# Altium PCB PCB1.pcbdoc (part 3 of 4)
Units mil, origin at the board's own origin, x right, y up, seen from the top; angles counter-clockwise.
Board outline 2559.1 x 3937 mil, 4 copper layers (Top Layer, Inner1, Inner2, Bottom Layer), stack 102.8 mil thick; 377 components, 358 nets, 1639 pads, 361 vias.
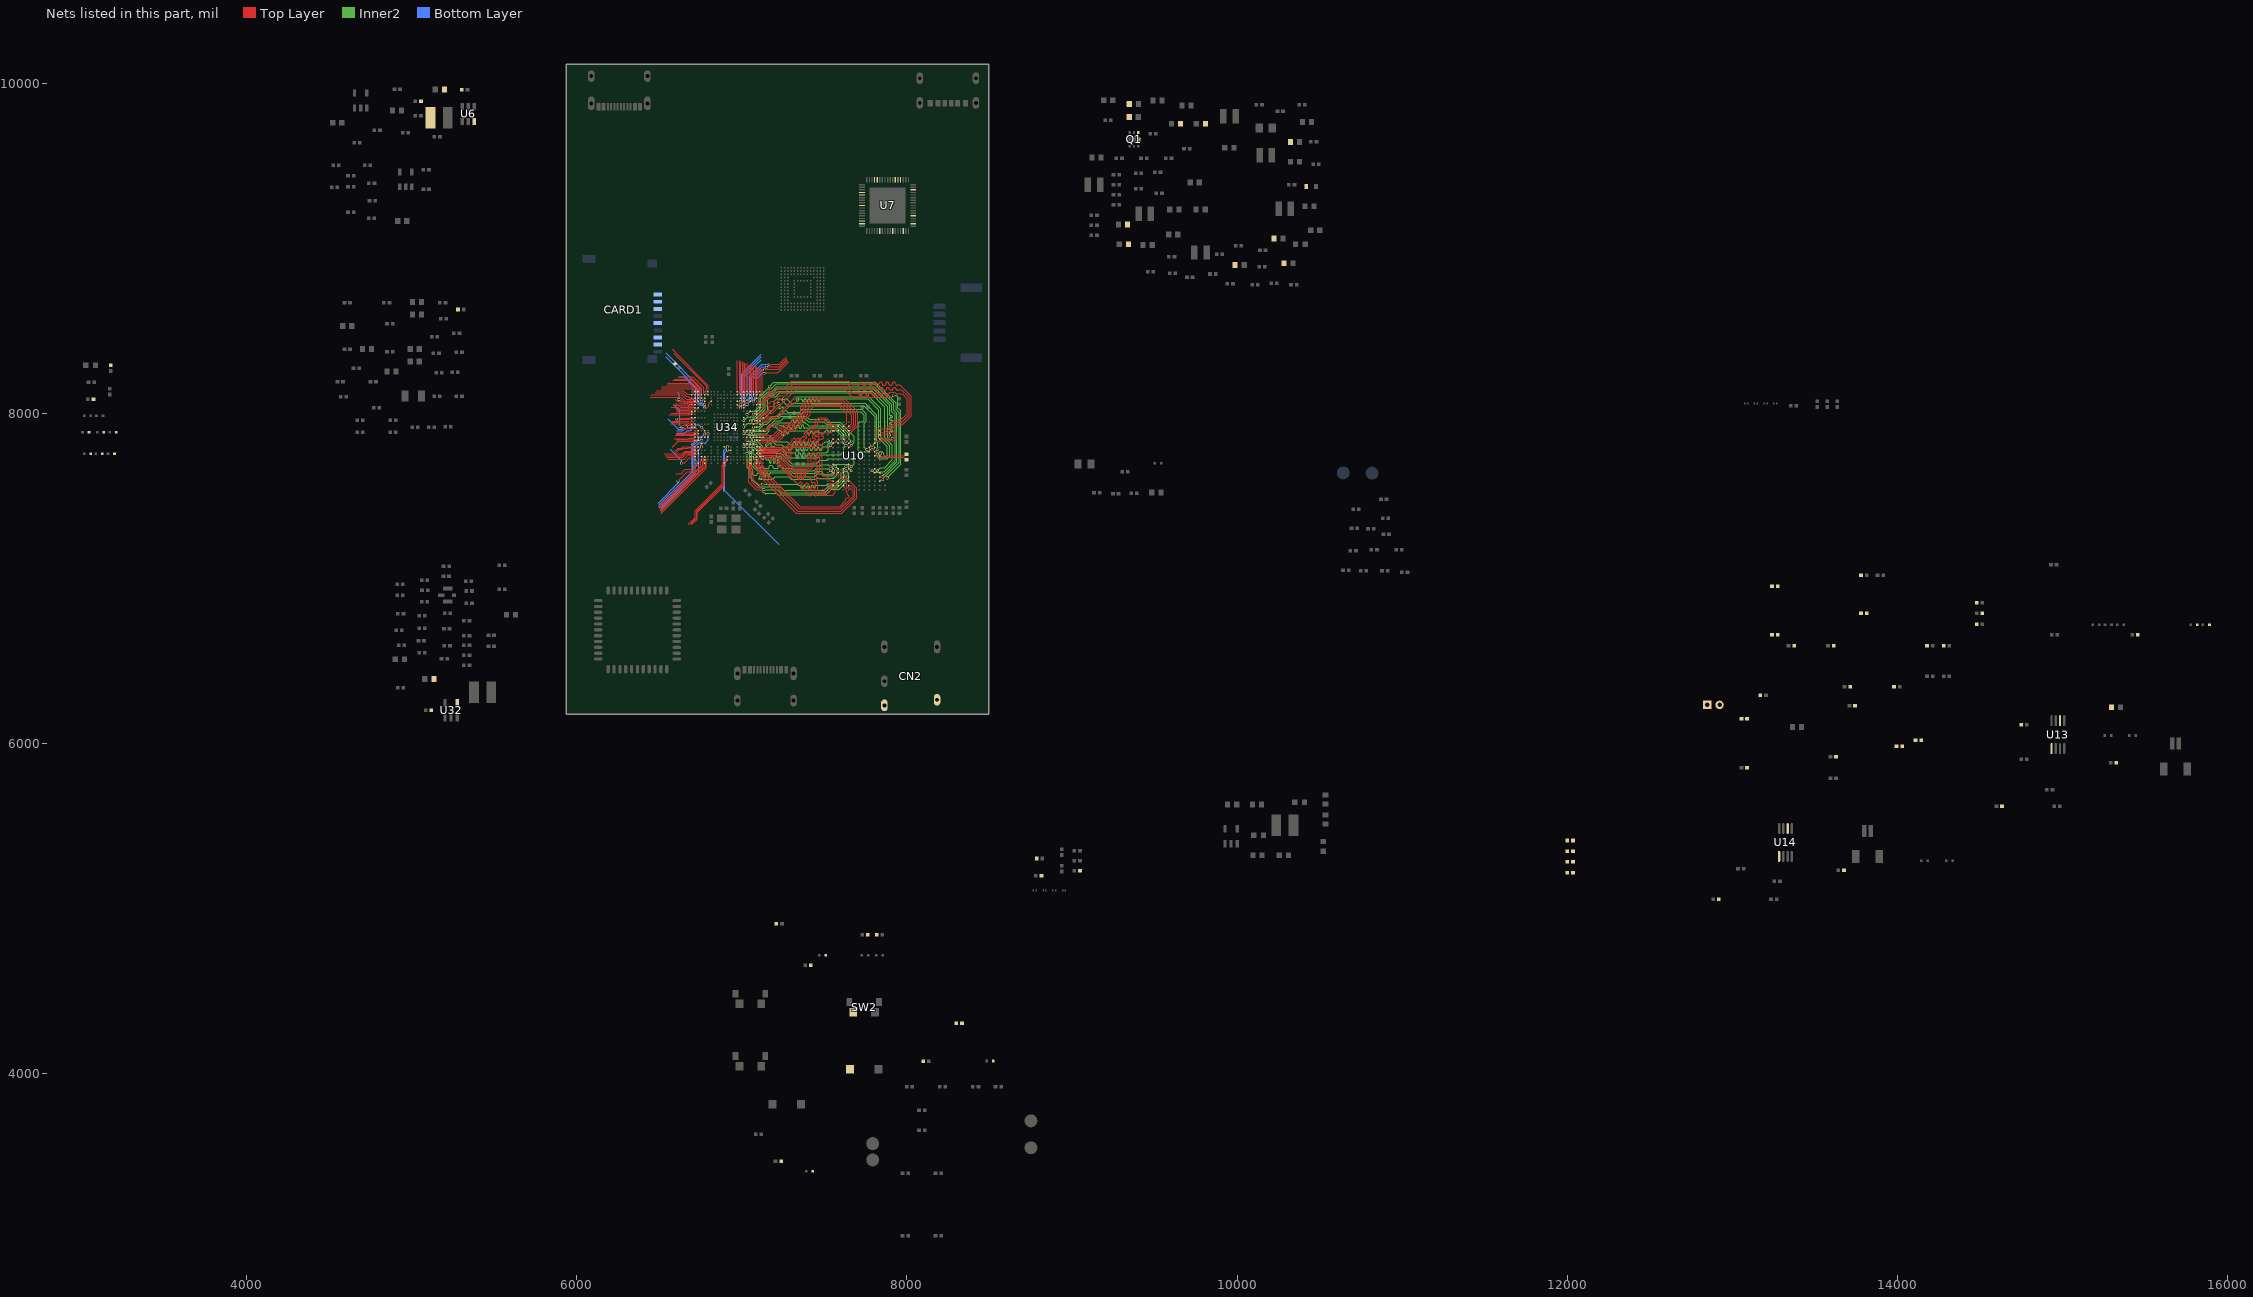
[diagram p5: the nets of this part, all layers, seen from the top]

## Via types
v1: diameter 16, hole 11.8, Top Layer to Bottom Layer, 361 vias

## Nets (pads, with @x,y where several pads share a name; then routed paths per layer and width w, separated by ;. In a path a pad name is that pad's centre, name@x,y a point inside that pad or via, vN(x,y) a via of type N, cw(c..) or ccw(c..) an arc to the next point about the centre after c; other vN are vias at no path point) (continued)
HP-DET: R116.2 U34.C11 | length 272.9
  Top Layer w3.5: v1(6624,7918.6) 6639.2,7903.4 6671.6,7903.4 6673,7904.8 6727.1,7904.8 U34.C11@6736.9,7895
  Bottom Layer w4: 6587.2,8052.4 6624,8015.6 v1(6624,7918.6)
HPOUTFB: C169.1 C170.2 C172.1 R111.1 R112.1 R119.2 U34.B17 | length 149.9
  Top Layer w3.5: 6663.1,7996.4 6678.1,7996.4 6684.9,8003.2 6707.3,8003.2 U34.B17@6717.2,8013.1
  Top Layer w4: 6574.2,7996.4 6663.1,7996.4
HPOUTFB-1: CN2.2 D26.2 R110.2 R111.2
HPOUTL: C157.2 C175.1 R115.1 U34.A17 | length 97.5
  Top Layer w3.5: 6662.5,8005.1 6676.8,8005.1 6684.8,8013.1 U34.A17@6697.5,8013.1
  Top Layer w4: 6603.3,8005.1 6662.5,8005.1
HPOUTR: C152.2 C174.1 R117.1 U34.A16 | length 137.8
  Top Layer w3.5: 6663.8,7988.6 6680.7,7988.6 6685.5,7993.4 U34.A16@6697.5,7993.4
  Top Layer w4: 6561.7,7988.6 6663.8,7988.6
HS-MIC: C168.1 C171.2 C172.2 R109.1 R110.1 R113.1 U34.A15 | length 94.4
  Top Layer w3.5: 6681.2,7969.6 6684.4,7969.6 6688.5,7973.7 U34.A15@6697.5,7973.7
  Top Layer w4: v1(6606.9,7964.5) 6619.8,7964.5 6624.8,7969.6 6681.2,7969.6
HS-MIC-1: CN2.1 D25.2 R109.2 R112.2
I2S0-BCLK: U34.D2 | length 396.5
  Top Layer w3.5: 6748.3,7677.3 6753.1,7682.1 6753.1,7709.4 6756.6,7712.9 U34.D2@6756.6,7717.8
  Top Layer w4: 6497.8,7430.9 6690.8,7623.8 6694.8,7623.8 6748.3,7677.3
I2S0-DIN: U34.E1 | length 405.1
  Top Layer w3.5: 6768.2,7662.4 6768.5,7662.4 6776.3,7670.1 U34.E1@6776.3,7698.1
  Top Layer w4: 6509.5,7403.7 6768.2,7662.4
I2S0-DOUT: R123.1 U13.1 U14.1 U34.E2 | length 417.9
  Top Layer w3.5: 6760.3,7665.6 6767.1,7672.4 6767.1,7703.6 6773.4,7710 6773.4,7715.4 U34.E2@6776.1,7718
  Top Layer w4: 6506.5,7411.8 6760.3,7665.6
I2S0-LRCK: U34.E3 | length 460.1
  Top Layer w3.5: 6775.5,7657.6 6785.5,7667.6 6785.5,7714.2 6786.1,7714.8 6786.1,7727.7 U34.E3@6776.3,7737.5
  Top Layer w4: 6512.6,7394.8 6775.5,7657.6
I2S0-MCLK: U34.D3 | length 430.3
  Top Layer w3.5: 6756.1,7674.5 6760.1,7678.5 6760.1,7706.5 6766.4,7712.9 6766.4,7727.6 U34.D3@6756.6,7737.5
  Top Layer w4: 6502.2,7420.6 6756.1,7674.5
KD-EINT: R99.2 R100.1 R101.2 U34.B3 | length 210.2
  Top Layer w3.5: v1(6634.9,7698.3) 6650.8,7698.3 6680.5,7728 6702.2,7728 6710,7735.8 U34.B3@6716.3,7735.8
  Bottom Layer w4: 6566.2,7783.1 6634.9,7714.4 v1(6634.9,7698.3)
LCD-CLK: U34.W21 | length 387.5
  Top Layer w4: U34.W21@7051.8,8091.8 v1(7071.5,8091.8) ; v1(7137,8262.4) 7221.6,8262.4 7276.9,8317.7
  Bottom Layer w4: v1(7071.5,8091.8) 7071.5,8209.4 7124.6,8262.4 v1(7137,8262.4)
LCD-D2: U34.V22 | length 187.7
  Top Layer w3.5: U34.V22@7032.2,8111.5 7042,8121.4 7042,8154.3
  Top Layer w4: 7042,8154.3 7042,8295.2
LCD-D3: U34.V23 | length 168.2
  Top Layer w4: U34.V23@7032.2,8131.2 7032.2,8299.4
LCD-D4: U34.W22 | length 182.1
  Top Layer w3.5: U34.W22@7051.8,8111.5 7061.7,8121.4 7061.7,8150.4
  Top Layer w4: 7061.7,8150.4 7061.7,8289.5
LCD-D5: U34.W23 | length 161.2
  Top Layer w4: U34.W23@7051.8,8131.2 7051.8,8292.4
LCD-D6: U34.AA22 | length 168.1
  Top Layer w3.5: U34.AA22@7091.2,8111.5 7101,8121.4 7101,8146.6
  Top Layer w4: 7101,8146.6 7101,8275.6
LCD-D7: U34.AA23 | length 147.4
  Top Layer w4: U34.AA23@7091.2,8131.2 7091.2,8278.6
LCD-D10: U34.Y22 | length 174.5
  Top Layer w3.5: U34.Y22@7071.5,8111.5 7081.4,8121.4 7081.4,8152.5
  Top Layer w4: 7081.4,8152.5 7081.4,8281.9
LCD-D11: U34.Y23 | length 154.6
  Top Layer w4: U34.Y23@7071.5,8131.2 7071.5,8285.8
LCD-D12: U34.AB22 | length 159.9
  Top Layer w3.5: U34.AB22@7110.9,8111.5 7120.7,8121.3 7120.7,8152.4
  Top Layer w4: 7120.7,8152.4 7120.7,8267.3
LCD-D13: U34.AB23 | length 140.8
  Top Layer w4: U34.AB23@7110.9,8131.2 7110.9,8272
LCD-D14: U34.R22 | length 210.3
  Top Layer w4: U34.R22@6973.1,8111.5 6984,8122.5 6984,8317.3
LCD-D15: U34.R23 | length 187.5
  Top Layer w4: U34.R23@6973.1,8131.2 6973.1,8318.7
LCD-D18: U34.T21 | length 222.7
  Top Layer w3.5: U34.T21@6992.8,8091.8 7002.6,8101.7 7002.6,8154.6
  Top Layer w4: 7002.6,8154.6 7002.6,8310.5
LCD-D19: U34.T22 | length 201.7
  Top Layer w4: U34.T22@6992.8,8111.5 6992.8,8313.2
LCD-D20: U34.U22 | length 195.9
  Top Layer w3.5: U34.U22@7012.5,8111.5 7022.3,8121.4 7022.3,8152.2
  Top Layer w4: 7022.3,8152.2 7022.3,8303.4
LCD-D21: U34.U23 | length 176.1
  Top Layer w4: U34.U23@7012.5,8131.2 7012.5,8307.3
LCD-D22: U34.U21 | length 152.2
  Top Layer w4: U34.U21@7012.5,8091.8 v1(7032.2,8091.8)
  Bottom Layer w4: v1(7032.2,8091.8) 7032.2,8224.3
LCD-D23: U34.U20 | length 365.8
  Top Layer w4: v1@6992.8,8052.5 U34.U20@7012.5,8072.2
  Bottom Layer w4: v1@6992.8,8052.5 7006.6,8066.3 7006.6,8229.2 7116.6,8339.2
  other v1: 6992.5,8052.5
LCD-DE: U34.W20 | length 397.1
  Top Layer w4: U34.W20@7051.8,8072.2 v1(7071.5,8072.2) ; v1(7136.3,8242) 7215.9,8242 7283.3,8309.4
  Bottom Layer w4: v1(7071.5,8072.2) 7086.7,8087.4 7086.7,8202.3 7126.1,8241.7 7136,8241.7 v1(7136.3,8242)
LCD-HSYNC: U34.U19 | length 451.6
  Top Layer w4: U34.U19@7012.5,8052.5 v1(7032.2,8072.2) ; v1(7167.6,8294.2) 7225.9,8294.2 7267.3,8335.6
  Bottom Layer w4: v1@7032.2,8072.3 7045.7,8085.8 7045.7,8221.7 7118.2,8294.2 v1(7167.6,8294.2)
LCD-PWM: U34.R19 | length 371.5
  Top Layer w4: U34.R19@6973.1,8052.5 v1(6992.8,8032.8)
  Bottom Layer w4: v1(6992.8,8032.8) 7017.7,8057.7 7017.7,8225 7117.5,8324.8
LCD-RST: U34.R20 | length 353.2
  Top Layer w4: U34.R20@6973.1,8072.2 v1(6992.8,8072.2)
  Bottom Layer w4: v1(6992.8,8072.2) 6996.8,8076.2 6996.8,8235.4 7116.1,8354.6
LCD-VSYNC: U34.U18 | length 462.3
  Top Layer w4: U34.U18@7012.5,8032.8 v1(7032.2,8052.5) ; v1(7150.7,8278.2) 7224.1,8278.2 7272.8,8326.9
  Bottom Layer w4: v1(7032.2,8052.5) 7057.3,8077.6 7057.3,8214.4 7121.1,8278.2 v1(7150.7,8278.2)
LRADC: C158.2 D38.2 R131.1 R134.2 R135.1 U34.E11 | length 204.5
  Top Layer w4: v1(6756.6,7914.7) U34.E11@6776.3,7895
  Bottom Layer w4: 6606.6,7878.4 6653.5,7878.4 6669.2,7894.1 6686.8,7894.1 6721.4,7928.7 6742,7928.7 6756,7914.7 v1(6756.6,7914.7)
MBIAS: C180.1 R122.2 U34.B15 | length 146.2
  Top Layer w3.5: 6680.7,7959.2 6685.6,7959.2 6690.3,7963.9 6707.3,7963.9 U34.B15@6717.2,7973.7
  Top Layer w4: 6580.9,7949.8 6621.1,7949.8 6630.5,7959.2 6680.7,7959.2
MCSI-MCLK: R29.1
MCSI-RST-F: U34.E22 | length 223.6
  Top Layer w3.5: 6765.8,8152.4 6765.8,8121.9 U34.E22@6776.3,8111.5
  Top Layer w4: 6618.1,8219.8 6703,8219.8 6765.8,8157 6765.8,8152.4
MCSI-RST-R: U34.E21 | length 413.8
  Top Layer w4: v1(6756.8,8071.5) 6756.8,8072.4 U34.E21@6776.3,8091.8
  Bottom Layer w4: 6538.8,8366.6 6746.6,8158.8 6746.6,8081.7 v1(6756.8,8071.5)
MCSI-SCK: U34.E20 | length 415.2
  Top Layer w4: v1(6776.3,8052.5) U34.E20@6776.3,8072.2
  Bottom Layer w4: 6543.1,8338.3 6631.4,8250 6632.8,8250 6640.7,8242 6640.7,8240.7 6735.1,8146.3 6735.1,8072.6 6750,8057.6 6771.1,8057.6 v1(6776.3,8052.5)
MCSI-SDA: U34.G20 | length 344.5
  Top Layer w4: v1(6776.3,8032.8) 6776.8,8032.2 6789.6,8032.2 6797.7,8040.3 6797.7,8054.4 6815.4,8072.2 U34.G20@6815.6,8072.2
  Bottom Layer w4: 6618.9,8219.4 6650.7,8219.4 6722.3,8147.7 6722.3,8070.2 6745,8047.6 6761.5,8047.6 v1(6776.3,8032.8)
MCSI-STBY-F: U34.F22 | length 336.9
  Top Layer w3.5: 6786.1,8148.1 6786.1,8121.3 U34.F22@6795.9,8111.5
  Top Layer w4: 6589.1,8362.7 6786.1,8165.7 6786.1,8148.1
MCSI-STBY-R: U34.F23 | length 344.6
  Top Layer w4: 6579.4,8386.1 6795.9,8169.6 U34.F23@6795.9,8131.2
MCSIA-CKN: U34.A22 | length 224.5
  Top Layer w4: 6482.2,8132.6 6650.6,8132.6 6672.3,8110.9 6696.9,8110.9 U34.A22@6697.5,8111.5
MCSIA-CKP: U34.A21 | length 232.5
  Top Layer w4: 6476.6,8119.7 6645.9,8119.7 6666.7,8098.9 6677.1,8098.9 6684.2,8091.8 U34.A21@6697.5,8091.8
MCSIA-D0N: U34.D21 | length 245
  Top Layer w3.5: 6746.7,8143.4 6746.8,8101.6 U34.D21@6756.6,8091.8
  Top Layer w4: 6581.8,8195.3 6699.8,8195.3 6746.7,8148.4 6746.7,8143.4
MCSIA-D0P: U34.D22 | length 228.9
  Top Layer w4: 6590.4,8206.3 6701.8,8206.3 6756.6,8151.5 U34.D22@6756.6,8111.5
MCSIA-D1N: U34.C22 | length 227.3
  Top Layer w3.5: 6727,8139.7 6727,8121.4 U34.C22@6736.9,8111.5
  Top Layer w4: 6545.5,8169.7 6698.9,8169.7 6727,8141.5 6727,8139.7
MCSIA-D1P: U34.C23 | length 215.2
  Top Layer w4: 6551,8182.3 6699.6,8182.3 6736.9,8145 U34.C23@6736.9,8131.2
MCSIA-D2N: U34.B21 | length 282
  Top Layer w3.5: 6663.2,8086.2 6666.8,8082.7 6703.1,8082.7 6712.2,8091.8 U34.B21@6717.2,8091.8
  Top Layer w4: 6449.4,8108 6641.4,8108 6663.2,8086.2
MCSIA-D2P: U34.C21 | length 309.8
  Top Layer w3.5: 6662,8073.1 6672.1,8073.1 6674.6,8075.7 6705.9,8075.7 6712.3,8082 6727.1,8082 U34.C21@6736.9,8091.8
  Top Layer w4: 6444.8,8097.1 6632.4,8097.1 6656.4,8073.1 6662,8073.1
MCSIA-D3N: U34.B22 | length 227.1
  Top Layer w3.5: 6670.8,8144.9 6699,8144.9 6707.3,8136.5 6707.3,8121.4 U34.B22@6717.2,8111.5
  Top Layer w4: 6512.8,8144.9 6670.8,8144.9
MCSIA-D3P: U34.B23 | length 215.6
  Top Layer w4: 6516.9,8157.7 6698.1,8157.7 6717.2,8138.7 U34.B23@6717.2,8131.2
MCSIB-CKN: U34.A19 | length 108.1
  Top Layer w3.5: 6674.9,8045.9 6675.3,8045.9 6681.9,8052.5 U34.A19@6697.5,8052.5
  Top Layer w4: 6596.9,8057.5 6624.5,8057.5 6636.1,8045.9 6674.9,8045.9
MCSIB-CKP: U34.B19 | length 143.4
  Top Layer w3.5: 6675.7,8036.2 6682.4,8042.9 6707.6,8042.9 U34.B19@6717.2,8052.5
  Top Layer w4: 6585,8047 6619.9,8047 6630.7,8036.2 6675.7,8036.2
MCSIB-D0N: U34.B20 | length 160
  Top Layer w3.5: 6667.7,8064 6673.1,8064 6677.8,8068.7 6709.1,8068.7 6712.6,8072.2 U34.B20@6717.2,8072.2
  Top Layer w4: v1(6619.3,8082.9) 6619.6,8083.1 6631.5,8083.1 6650.7,8064 6667.7,8064
  Bottom Layer w4: 6608.5,8129.2 6619.3,8118.3 v1(6619.3,8082.9)
MCSIB-D0P: U34.C20 | length 157.6
  Top Layer w3.5: 6672.3,8055 6674.5,8055 6681.1,8061.7 6712,8061.7 6712,8062.3 6727,8062.3 U34.C20@6736.9,8072.2
  Top Layer w4: 6598.2,8082.5 6612,8068.7 6629.8,8068.7 6643.5,8055 6672.3,8055
MCSIB-D1N: U34.B18 | length 151.4
  Top Layer w3.5: 6677.7,8026.4 6684.1,8032.8 U34.B18@6717.2,8032.8
  Top Layer w4: 6572.7,8036.7 6612.9,8036.7 6623.3,8026.4 6677.7,8026.4
MCSIB-D1P: U34.C18 | length 148.4
  Top Layer w3.5: 6676.9,8015.5 6682.1,8020.7 6685.7,8020.7 6689.2,8024.2 6707.2,8024.2 6708.5,8022.9 6727,8022.9 U34.C18@6736.9,8032.8
  Top Layer w4: 6601.4,8026.9 6612.9,8015.5 6676.9,8015.5
MIC1N-MIC: C153.2 C154.2 C177.1 MIC1.2 R127.2
MIC1P-MIC: C177.2 C178.1 C179.2 MIC1.1 R124.2
MICIN1N: C153.1 U34.A13 | length 134.6
  Top Layer w4: 6569,7932.1 6631.9,7932.1 6640.5,7940.7 6675,7940.7 6681.4,7934.4 U34.A13@6697.5,7934.4
MICIN1P: C179.1 U34.B13 | length 151.4
  Top Layer w3.5: 6680,7949.2 6685,7944.2 6707.4,7944.2 U34.B13@6717.2,7934.4
  Top Layer w4: 6575.3,7941 6628.6,7941 6636.8,7949.2 6680,7949.2
MICIN2N: C169.2 U34.A12 | length 103
  Top Layer w4: v1(6663.7,7918) 6667.1,7914.7 U34.A12@6697.5,7914.7
  Bottom Layer w4: 6607.6,7894.4 6643.5,7894.4 6663.7,7914.6 v1(6663.7,7918)
MICIN2P: C168.2 U34.B12 | length 219.8
  Top Layer w3.5: 6669.1,7932.4 6677,7924.5 6707.3,7924.5 U34.B12@6717.2,7914.7
  Top Layer w4: v1(6644,7919) 6657.5,7932.4 6669.1,7932.4
  Bottom Layer w4: 6550.9,7967.5 6616.2,7902.2 6638.5,7902.2 6644,7907.7 v1(6644,7919)
MOTOR-DRV: U34.C1 | length 361.4
  Top Layer w4: v1(6614.1,7588.5) 6614.1,7588.6 6668.8,7643.3 6689.9,7643.3 6736.9,7690.3 U34.C1@6736.9,7698.1
  Bottom Layer w4: 6490.5,7451.1 6614.1,7574.7 v1(6614.1,7588.5)
MPU6050-INT: U34.M2 | length 480.5
  Top Layer w3.5: 6887,7556.1 6894.8,7563.9 6894.8,7674.5 6903.7,7683.4 6903.7,7702.7 6914,7713 U34.M2@6914,7717.8
  Top Layer w4: 6698.8,7326.4 6731.8,7359.4 6731.8,7400.9 6887,7556.1
PA-VDD: C151.2 C156.2 L10.1 U13.6 U14.6
PH2: U34.B6 | length 132.5
  Top Layer w4: 6596.1,7769 6615.9,7788.8 6634.9,7788.8 6642.7,7796.6 U34.B6@6717.2,7796.6
PH3: U34.B5 | length 196.3
  Top Layer w3.5: 6638.1,7750.5 6655.3,7767.7 6702.2,7767.7 6711.3,7776.9 U34.B5@6717.5,7776.9
  Top Layer w4: 6532.2,7750.5 6638.1,7750.5
PH4: U34.C6 | length 151.9
  Top Layer w3.5: 6672.1,7786.7 6727,7786.7 U34.C6@6736.9,7796.6
  Top Layer w4: 6600.3,7759.7 6621.3,7780.7 6638.6,7780.7 6644.6,7786.7 6672.1,7786.7
PH5: U34.C5 | length 213
  Top Layer w3.5: 6639.9,7741.3 6659.3,7760.7 6705.1,7760.7 6711.4,7767 6727,7767 U34.C5@6736.9,7776.9
  Top Layer w4: 6538.6,7741.3 6639.9,7741.3
PH6: U34.F9 | length 612.4
  Top Layer w4: U34.F9@6795.9,7855.6 v1(6795.9,7875.3)
  Bottom Layer w4: 6508.9,7425.8 6716.5,7633.4 6716.5,7798.1 6736.8,7818.4 6778.4,7818.4 6795.9,7835.9 v1(6795.9,7875.3)
PH7: U34.C4 | length 202.2
  Top Layer w3.5: 6667.8,7738.2 6676.3,7746.7 6710.9,7746.7 6710.9,7747.3 6728.7,7747.3 U34.C4@6738.5,7757.1
  Top Layer w4: 6551,7722.4 6652,7722.4 6667.8,7738.2
PH8: U34.E9 | length 578.3
  Top Layer w4: U34.E9@6776.3,7855.6 v1(6776.3,7875.3)
  Bottom Layer w4: 6495.5,7439.5 6699.1,7643.1 6699.1,7809.2 6745.8,7856 6756.3,7856 6775.6,7875.3 v1(6776.3,7875.3)
PH9: U34.D9 | length 540.9
  Top Layer w4: v1(6756.6,7835.9) U34.D9@6756.6,7855.6
  Bottom Layer w4: 6500.8,7431 6707.8,7637.9 6707.8,7804.7 6739,7835.9 v1(6756.6,7835.9)
PH10: U34.B4 | length 181.8
  Top Layer w3.5: 6643.4,7732.5 6664.5,7753.7 6708,7753.7 6710.6,7756.3 6716.3,7756.3 U34.B4@6717.2,7757.2
  Top Layer w4: 6545.7,7732.5 6643.4,7732.5
PH11: U34.D7 | length 506.7
  Top Layer w4: v1(6756.6,7796.6) U34.D7@6756.6,7816.3
  Bottom Layer w4: 6509.2,7412.1 6739.3,7642.3 6739.3,7779.4 v1(6756.6,7796.6)
PH13: U34.B2 | length 179.7
  Top Layer w3.5: 6717.3,7683.4 6727,7693.1 6727,7709.9 U34.B2@6719.4,7717.5
  Top Layer w4: 6599.2,7634.4 6632.9,7634.4 6656,7657.5 6691.4,7657.5 6717.3,7683.4
PMU-SCK: U7.47 U34.N5 | length 737
  Top Layer w4: v1@6914,7776.9 U34.N5@6933.7,7776.9
  Bottom Layer w4: v1(6914.1,7776.9) 6898.2,7761 6898.2,7530.9 7226.8,7202.3
PMU-SDA: U7.48 U34.L6 | length 301.8
  Top Layer w4: U34.L6@6894.4,7796.6 v1@6914.2,7796.6
  Bottom Layer w4: 6890.7,7524.4 6890.7,7773 v1(6914.3,7796.6)
PS: C59.2 C60.1 C67.2 C68.2 C71.1 C72.1 C80.1 C85.2 C87.2 C94.1 C95.1 C101.1 C164.2 L3.2 LED1.2 Q1.4 Q1.8 R33.2 R169.2 U6.3 U7.6 U7.11 U7.15 U7.19 U7.22 U7.32 U7.38 U7.39 U7.40 U7.55 U7.56 U7.66 U7.67 U32.4
PWRON: C182.1 R141.1 U7.60
PWRON-KEY: D37.2 R141.2 SW2.3
RESET-KEY: D36.2 R140.2 SW4.1
S-TWI1-SCK: U34.L1 | length 456.7
  Top Layer w3.5: 6872.1,7551.8 6887.8,7567.5 6887.8,7677.4 6892.1,7681.7 6892.1,7692.6 6894.4,7694.8 U34.L1@6894.4,7698.1
  Top Layer w4: 6687.4,7327.1 6723.5,7363.3 6723.5,7403.2 6872.1,7551.8
S-TWI1-SDA: U34.M3 | length 517.2
  Top Layer w3.5: 6878.9,7569.9 6880.8,7571.8 6880.8,7680.3 6885.1,7684.6 6885.1,7704 6889.1,7708 6899.1,7708 6904.2,7713.2 6904.2,7727.7 U34.M3@6914,7737.5
  Top Layer w4: 6674.3,7325.4 6714.3,7365.4 6714.3,7405.3 6878.9,7569.9
SA0: U10.R2 U34.AB19 | length 1412.4
  Top Layer w3.5: U34.AB19@7110.2,8052.3 7116.1,8052.3 7126.5,8062.8 7137.4,8062.8
  Top Layer w4: 7137.4,8062.8 7201.2,8126.6 7262.4,8126.6 7307.1,8171.2 7645.8,8171.2 7677.6,8139.5 7707.9,8139.5 ccw(c7707.9,8146.4) 7714.8,8146.4 cw(c7721.7,8146.4) 7721.7,8153.3 ; 7721.7,8153.2 7727.9,8153.2 ; 7727.9,8153.3 cw(c7727.9,8146.4) 7734.8,8146.4 ccw(c7741.7,8146.4) 7741.7,8139.5 7747.9,8139.5 ccw(c7747.9,8146.4) 7754.8,8146.4 cw(c7761.7,8146.4) 7761.7,8153.3 ; 7761.7,8153.2 7767.9,8153.2 ; 7767.9,8153.3 cw(c7767.9,8146.4) 7774.8,8146.4 ccw(c7781.7,8146.4) 7781.7,8139.5 7787.9,8139.5 ccw(c7787.9,8146.4) 7794.8,8146.4 cw(c7801.7,8146.4) 7801.7,8153.3 ; 7801.7,8153.2 7807.9,8153.2 ; 7807.9,8153.3 cw(c7807.9,8146.4) 7814.8,8146.4 ccw(c7821.7,8146.4) 7821.7,8139.5 7827.9,8139.5 ccw(c7827.9,8146.4) 7834.8,8146.4 cw(c7841.7,8146.4) 7841.7,8153.3 ; U10.R2@7836.8,7894.8 7849.9,7881.8 7867.9,7881.8 7932,7945.9 7970.2,7945.9 8014.3,7989.9 8014.3,8095.5 7970.3,8139.5 7941.7,8139.5 cw(c7941.7,8146.4) 7934.8,8146.4 ccw(c7927.9,8146.4) 7927.9,8153.3 ; 7841.7,8153.2 7847.9,8153.2 ; 7847.9,8153.3 cw(c7847.9,8146.4) 7854.8,8146.4 ccw(c7861.7,8146.4) 7861.7,8139.5 7867.9,8139.5 ccw(c7867.9,8146.4) 7874.8,8146.4 cw(c7881.7,8146.4) 7881.7,8153.3 ; 7881.7,8153.2 7887.9,8153.2 ; 7887.9,8153.3 cw(c7887.9,8146.4) 7894.8,8146.4 ccw(c7901.7,8146.4) 7901.7,8139.5 7907.9,8139.5 ccw(c7907.9,8146.4) 7914.8,8146.4 cw(c7921.7,8146.4) 7921.7,8153.3 ; 7921.7,8153.2 7927.9,8153.2
SA1: U10.P2 U34.AA19 | length 1513.5
  Top Layer w3.5: U34.AA19@7092.5,8054.2 7100.6,8062.3 7115.7,8062.3 7126.4,8073 7132,8073
  Top Layer w4: 7132,8073 7204.2,8145.2 7253.3,8145.2 7297.6,8189.5 7651.6,8189.5 7672.4,8168.6 7701.9,8168.6 ; 7701.9,8168.7 ccw(c7701.9,8178.4) 7711.6,8178.4 ; 7711.7,8178.4 cw(c7721.4,8178.4) 7721.4,8188.1 7721.9,8188.1 cw(c7721.9,8178.4) 7731.6,8178.4 ; 7731.7,8178.4 ccw(c7741.4,8178.4) 7741.4,8168.7 ; 7741.4,8168.6 7741.9,8168.6 ; 7741.9,8168.7 ccw(c7741.9,8178.4) 7751.6,8178.4 ; 7751.7,8178.4 cw(c7761.4,8178.4) 7761.4,8188.1 7761.9,8188.1 cw(c7761.9,8178.4) 7771.6,8178.4 ; 7771.7,8178.4 ccw(c7781.4,8178.4) 7781.4,8168.7 ; 7781.4,8168.6 7781.9,8168.6 ; 7781.9,8168.7 ccw(c7781.9,8178.4) 7791.6,8178.4 ; 7791.7,8178.4 cw(c7801.4,8178.4) 7801.4,8188.1 7801.9,8188.1 cw(c7801.9,8178.4) 7811.6,8178.4 ; 7811.7,8178.4 ccw(c7821.4,8178.4) 7821.4,8168.7 ; 7821.4,8168.6 7821.9,8168.6 ; 7821.9,8168.7 ccw(c7821.9,8178.4) 7831.6,8178.4 ; 7831.7,8178.4 cw(c7841.4,8178.4) 7841.4,8188.1 7841.9,8188.1 cw(c7841.9,8178.4) 7851.6,8178.4 ; U10.P2@7836.8,7869.2 7873.2,7869.2 7935,7931 7973.3,7931 8026.7,7984.4 8026.7,8102.1 7960.2,8168.6 7941.4,8168.6 ; 7851.7,8178.4 ccw(c7861.4,8178.4) 7861.4,8168.7 ; 7861.4,8168.6 7861.9,8168.6 ; 7861.9,8168.7 ccw(c7861.9,8178.4) 7871.6,8178.4 ; 7871.7,8178.4 cw(c7881.4,8178.4) 7881.4,8188.1 7881.9,8188.1 cw(c7881.9,8178.4) 7891.6,8178.4 ; 7891.7,8178.4 ccw(c7901.4,8178.4) 7901.4,8168.7 ; 7901.4,8168.6 7901.9,8168.6 ; 7901.9,8168.7 ccw(c7901.9,8178.4) 7911.6,8178.4 ; 7911.7,8178.4 cw(c7921.4,8178.4) 7921.4,8188.1 7921.9,8188.1 cw(c7921.9,8178.4) 7931.6,8178.4 ; 7931.7,8178.4 ccw(c7941.4,8178.4) 7941.4,8168.7
SA2: U10.N2 U34.U15 | length 1419.1
  Top Layer w4: v1(7012.5,7955.3) U34.U15@7012.5,7973.7 ; U10.N2@7836.8,7843.6 7883.7,7843.6 7896.2,7856.2 v1(7896.2,7869.8)
  Inner2 w4: v1(7012.5,7955.3) 7035.5,7978.3 7082.1,7978.3 7130.3,8026.6 7130.3,8088.1 7161.7,8119.5 7188.1,8119.5 7216.9,8148.4 7796.8,8148.4 7894.8,8050.4 7894.8,7992.7 ccw(c7901.8,7992.7) 7901.8,7985.7 7906.6,7985.7 cw(c7906.6,7978.7) 7906.6,7971.7 7901.8,7971.7 ccw(c7901.8,7964.7) 7901.8,7957.7 7906.6,7957.7 cw(c7906.6,7950.7) 7906.6,7943.7 7901.8,7943.7 ccw(c7901.8,7936.7) 7901.8,7929.7 7906.6,7929.7 cw(c7906.6,7922.7) 7906.6,7915.7 7901.8,7915.7 ccw(c7901.8,7908.7) 7901.8,7901.7 7906.6,7901.7 cw(c7906.6,7894.7) 7906.6,7887.7 7901.8,7887.7 ccw(c7901.8,7880.7) 7894.8,7880.7 7894.8,7871.2 v1(7896.2,7869.8)
SA3: U10.N3 U34.AB18 | length 1438
  Top Layer w4: U34.AB18@7110.9,8032.8 7137.7,8032.8 7174.7,8069.7 7191.3,8069.7 7226,8104.4 7264.7,8104.4 7315.5,8155.2 7640.6,8155.2 7670.4,8125.3 7702.2,8125.3 cw(c7702.2,8117.1) 7710.4,8117.1 ccw(c7718.6,8117.1) 7718.6,8108.9 7722.2,8108.9 ccw(c7722.2,8117.1) 7730.4,8117.1 cw(c7738.6,8117.1) 7738.6,8125.3 7742.2,8125.3 cw(c7742.2,8117.1) 7750.4,8117.1 ccw(c7758.6,8117.1) 7758.6,8108.9 7762.2,8108.9 ccw(c7762.2,8117.1) 7770.4,8117.1 cw(c7778.6,8117.1) 7778.6,8125.3 7782.2,8125.3 cw(c7782.2,8117.1) 7790.4,8117.1 ccw(c7798.6,8117.1) 7798.6,8108.9 7802.2,8108.9 ccw(c7802.2,8117.1) 7810.4,8117.1 cw(c7818.6,8117.1) 7818.6,8125.3 7822.2,8125.3 cw(c7822.2,8117.1) 7830.4,8117.1 ccw(c7838.6,8117.1) 7838.6,8108.9 7842.2,8108.9 ccw(c7842.2,8117.1) 7850.4,8117.1 cw(c7858.6,8117.1) 7858.6,8125.3 7862.2,8125.3 cw(c7862.2,8117.1) 7870.4,8117.1 ccw(c7878.6,8117.1) 7878.6,8108.9 7882.2,8108.9 ccw(c7882.2,8117.1) 7890.4,8117.1 cw(c7898.6,8117.1) 7898.6,8125.3 7930.2,8125.3 7941.5,8114 7974.8,8114 8001.8,8087 8001.8,7998.4 7962.9,7959.5 7928.2,7959.5 7876.1,7907.4 7825.8,7907.4 7819.8,7901.3 7819.8,7858.1 U10.N3@7805.3,7843.6
SA4: U10.M3 U34.Y13 | length 1479
  Top Layer w4: v1(7051.8,7954) U34.Y13@7071.5,7934.4 ; U10.M3@7805.3,7818.1 7818.1,7830.8 7928.6,7830.8 7932.6,7834.8 7932.6,7885.7 7928.6,7889.7 7921.4,7889.7 7916.6,7884.8 7916.6,7856.8 7912.6,7852.8 v1(7912.6,7847.9)
  Inner2 w4: v1(7051.8,7954) 7065.7,7967.9 7089,7967.9 7143.1,8022.1 7143.1,8084.8 7166.3,8107.9 7195.7,8107.9 7222.2,8134.5 7790.3,8134.5 7882.7,8042 7882.7,7853.2 7895.5,7840.4 7905.1,7840.4 v1(7912.6,7847.9)
SA5: U10.F3 U34.AA17 | length 1558
  Top Layer w4: v1@7071.5,7993.4 U34.AA17@7091.2,8013.1 ; v1(7789.6,7651.6) 7792.4,7651.6 U10.F3@7805.3,7664.5
  Inner2 w4: v1@7071.5,7993.4 7079.4,7993.4 7116.2,8030.2 7116.2,8090.1 7157.7,8131.6 7182.2,8131.6 7212,8161.4 7800.9,8161.4 7907.1,8055.2 7907.1,8012 7926.1,7993 7926.1,7710.1 7859.1,7643.1 7836.8,7643.1 7831.9,7638.2 7803,7638.2 v1(7789.6,7651.6)
  other v1: 7071.5,7992.9
SA6: U10.E3 U34.AB13 | length 1463.4
  Top Layer w3.5: v1(7071.5,7954) 7081.3,7944.2 7101,7944.2 U34.AB13@7110.9,7934.4
  Top Layer w4: U10.E3@7805.3,7638.9 7818.2,7651.8 v1(7821.1,7651.8)
  Inner2 w4: v1(7071.5,7954) 7094.7,7954 7155.8,8015.1 7155.8,8080.2 7172.3,8096.7 7203.5,8096.7 7228.4,8121.7 7783.4,8121.7 7867.3,8037.8 7867.3,7851.4 7911.5,7807.2 7911.5,7716.9 7865.2,7670.5 7839.8,7670.5 v1(7821.1,7651.8)
SA7: U10.E2 U34.W17 | length 1572.1
  Top Layer w4: v1@7031.9,7993.1 U34.W17@7051.5,8012.8 ; U10.E2@7836.8,7638.9 7847.4,7628.4 v1(7850.3,7628.4)
  Inner2 w4: v1@7031.9,7993.1 7048,8009.2 7074.8,8009.2 7103.3,8037.7 7103.3,8094.3 7153.5,8144.6 7175.5,8144.6 7205.1,8174.1 7805.9,8174.1 7920.3,8059.8 7920.3,8017.8 7938.9,7999.1 7938.9,7705.2 7862.1,7628.4 v1(7850.3,7628.4)
  other v1: 7031.9,7992.9
SA8: U10.D2 U34.AC15 | length 1488.5
  Top Layer w4: U34.AC15@7130.6,7973.7 7144.7,7973.7 7168.2,7997.3 7182.6,7997.3 7323.1,8137.8 7630.7,8137.8 7674.1,8094.4 7905.7,8094.4 v1(7918.3,8106.9) ; U10.D2@7836.9,7613.4 7838.1,7612.2 7877.4,7612.2 v1(7881.4,7608.2)
  Inner2 w4: v1(7881.4,7608.2) 7881.4,7610.4 7962.8,7691.8 7962.8,8014 7946.6,8030.3 7946.6,8099.5 7939.2,8106.9 v1(7918.3,8106.9)
SA9: U10.C2 U34.AA21 | length 1488.8
  Top Layer w3.5: U34.AA21@7091.4,8091.7 7104.1,8091.7 7114.2,8101.7 7144.8,8101.7 7167.5,8124.3
  Top Layer w4: 7167.5,8124.3 v1(7167.5,8161) ; U10.C2@7836.8,7587.7 7836.8,7588.4 7845.9,7597.4 v1(7853.6,7597.4)
  Inner2 w4: v1(7167.5,8161) 7193.7,8187.1 7808.6,8187.1 7932.8,8063 7932.8,8024.1 7951.5,8005.4 7951.5,7700.9 7853.6,7603.1 v1(7853.6,7597.4)
SCKE0: U10.K3 U34.AA16 | length 1045
  Top Layer w3.5: U34.AA16@7091.2,7993.4 7101.1,8003.3 7137.7,8003.3
  Top Layer w4: 7137.7,8003.3 7141.8,8003.3 7162.9,8024.3 7162.9,8034.7 7170.8,8042.6 7187.2,8042.6 7232.9,8088.3 v1(7252.7,8088.3) ; U10.K3@7805.3,7766.9 7818.2,7779.8 v1(7821.1,7779.8)
  Inner2 w4: v1(7252.7,8088.3) 7272,8088.3 7301,8059.3 7747.8,8059.3 7816.1,7991.1 7816.1,7829.7 7821.1,7824.7 v1(7821.1,7779.8)
SCKE1: U10.K4 U34.AA15 | length 1046.5
  Top Layer w3.5: U34.AA15@7091.2,7973.7 7101.1,7983.6 7118.5,7983.6 7124.4,7989.6 7139.3,7989.6
  Top Layer w4: 7139.3,7989.6 7144,7989.6 7168.5,8014.1 7181.5,8014.1 7225.3,8057.9 v1(7225.3,8060.2) ; v1(7758.1,7780) 7760.7,7780 U10.K4@7773.8,7766.9
  Inner2 w4: v1(7225.3,8060.2) 7225.8,8060.2 7231.6,8054.4 ; 7226.9,8039.9 7231.6,8044.5 ; 7226.95,8039.85 ccw(c7231.9,8034.9) 7236.85,8029.95 ; 7231.65,8044.55 ccw(c7226.7,8049.5) 7231.65,8054.45 ; 7236.8,8030 7241.5,8034.6 ; 7241.55,8034.65 cw(c7246.5,8029.7) 7251.45,8024.75 ; 7246.7,8020.1 7251.4,8024.7 ; 7246.75,8020.05 ccw(c7251.7,8015.1) 7256.65,8010.15 ; 7256.6,8010.2 7261.3,8014.8 ; 7261.35,8014.85 cw(c7266.3,8009.9) 7271.25,8014.85 ; 7271.2,8014.8 7281.7,8004.3 7348,8004.3 7363.9,8020.2 7730.3,8020.2 7754.1,7996.5 7754.1,7951.4 7742.8,7940.1 7742.8,7795.3 v1(7758.1,7780)
SCKN: R87.2 U10.J2 U34.AB14 | length 1486.5
  Top Layer w4: U34.AB14@7110.9,7954 7118.9,7946 7146.1,7946 7163,7963 7208.4,7963 7299.3,8053.8 7313.5,8053.8 v1(7339.7,8080) ; U10.J2@7836.8,7741.3 7849.7,7754.2 v1(7852.6,7754.2) 7867.8,7739 7985.5,7739 R87.2@7998.3,7751.7
  Inner2 w4: v1(7339.7,8080) 7346.1,8086.4 7359.6,8086.4 cw(c7359.6,8080.4) 7365.6,8080.4 7365.6,8077.9 ccw(c7371.6,8077.9) 7377.6,8077.9 7377.6,8080.4 cw(c7383.6,8080.4) 7389.6,8080.4 7389.6,8077.9 ccw(c7395.6,8077.9) 7401.6,8077.9 7401.6,8080.4 cw(c7407.6,8080.4) 7413.6,8080.4 7413.6,8077.9 ccw(c7419.6,8077.9) 7425.6,8077.9 7425.6,8080.4 cw(c7431.6,8080.4) 7437.6,8080.4 7437.6,8077.9 ccw(c7443.6,8077.9) 7449.6,8077.9 7449.6,8080.4 cw(c7455.6,8080.4) 7461.6,8080.4 7461.6,8077.9 ccw(c7467.6,8077.9) 7473.6,8077.9 7473.6,8080.4 cw(c7479.6,8080.4) 7479.6,8086.4 7763.4,8086.4 7827.3,8022.5 7827.3,7852.7 7879.9,7800.1 7879.9,7743.3 7868.6,7732 7841.6,7732 7834.7,7738.8 7834.7,7763.9 7839.4,7768.6 7848,7768.6 7852.6,7764 v1(7852.6,7754.2)
SCKP: R87.1 U10.J3 U34.AA14 | length 1484.2
  Top Layer w3.5: U34.AA14@7091.2,7954 7101.1,7963.9 7123,7963.9 7128.2,7958.7
  Top Layer w4: 7128.2,7958.7 7143,7958.7 7159.9,7975.6 7203.3,7975.6 7320,8092.4 v1(7322.9,8092.4) ; U10.J3@7805.3,7741.3 7818.2,7754.2 v1(7821.1,7754.2) 7820,7753.1 7820,7740 7830,7730.1 7985.9,7730.1 R87.1@7998.3,7717.6
  Inner2 w4: v1(7322.9,8092.4) 7329.7,8092.4 7335.8,8098.5 7770.2,8098.5 7839.1,8029.6 7839.1,7861.3 7894,7806.5 7894,7736.8 7877.3,7720.1 7837,7720.1 7821.1,7736.1 v1(7821.1,7754.2)
SCS0: U10.L3 U34.AA12 | length 1089.3
  Top Layer w4: v1(7071.2,7915.7) 7072.3,7914.7 U34.AA12@7091.2,7914.7 ; v1(7789.7,7778.3) 7791.2,7778.3 U10.L3@7805.3,7792.5
  Inner2 w4: v1(7071.2,7915.7) 7103.2,7915.7 7133,7945.5 7148.4,7945.5 7183,7980.1 7217.4,7980.1 7231.4,7994.1 7360.4,7994.1 7373,8006.7 7723.4,8006.7 7742.6,7987.5 7742.6,7956.1 7733.8,7947.3 7716.2,7947.3 7706.1,7937.2 7706.1,7777.1 7716.2,7767 7737.2,7767 7739.5,7764.6 7762.3,7764.6 7776,7778.3 v1(7789.7,7778.3)
SCS1: U10.L4 U34.U13 | length 1154.6
  Top Layer w4: v1(7012.2,7915.7) U34.U13@7012.2,7934.1 ; U10.L4@7773.8,7792.5 7787.7,7806.3 v1(7789.7,7806.3)
  Inner2 w4: v1(7012.2,7915.7) 7036.5,7940 7095.3,7940 7126.1,7970.8 7137.2,7970.8 7196.9,8030.5 7196.9,8072.2 7212.9,8088.2 7233.7,8088.2 7275.7,8046.3 7740.2,8046.3 7805.3,7981.2 7805.3,7822 v1(7789.7,7806.3)
SDC0-CLK: CARD1.5 D11.2 R30.1
SDC0-CMD: CARD1.3 D10.2 R90.1 U34.B9 | length 129
  Top Layer w3.5: 6675.5,7844.6 6706.2,7844.6 U34.B9@6717.2,7855.6
  Top Layer w4: 6592.8,7844.6 6675.5,7844.6
SDC0-D0: CARD1.7 D22.2 U34.C9 | length 144.7
  Top Layer w3.5: 6596.5,7864.8 6712.5,7864.8 6713.1,7865.5 6727,7865.5 ; 6727.1,7865.4 U34.C9@6736.9,7855.6
SDC0-D1: CARD1.8 D7.2 U34.B10 | length 115.3
  Top Layer w3.5: 6603.3,7871.8 6709.2,7871.8 6712.7,7875.3 U34.B10@6717.2,7875.3
SDC0-D2: CARD1.1 D8.2 U34.C8 | length 180.1
  Top Layer w3.5: 6675.3,7826.1 6727,7826.1 U34.C8@6736.9,7835.9
  Top Layer w4: 6575.8,7789.9 6612,7826.1 6675.3,7826.1
SDC0-D3: CARD1.2 D9.2 U34.B8 | length 114.5
  Top Layer w4: 6602.7,7835.9 U34.B8@6717.2,7835.9
SDC0-DET: R93.2 U34.C10 | length 134.1
  Top Layer w3.5: 6609.4,7878.8 6705.9,7878.8 6712.3,7885.1 6727.1,7885.1 U34.C10@6736.9,7875.3
SDQ0: U10.F11 U34.Y7 | length 824
  Top Layer w4: v1@7071.2,7797.6 7071.2,7816 U34.Y7@7071.5,7816.3 ; v1(7537.6,7677.4) 7540.5,7677.4 U10.F11@7553.4,7664.5
  Inner2 w4: v1@7071.2,7797.6 7083.6,7785.2 7089.5,7785.2 7102.3,7772.4 7102.3,7766.6 7096.5,7760.8 7096.5,7753.7 7104.1,7746.2 7110,7746.2 7113.9,7750.1 7121.8,7750.1 7126.4,7745.5 7126.4,7742.4 7117,7732.9 7117,7726.6 7122.6,7721 7129.8,7721 7135.6,7726.7 7142.1,7726.7 7149.9,7718.9 7161.2,7718.9 cw(c7161.2,7712.9) 7167.2,7712.9 7167.2,7704.3 ccw(c7173.2,7704.3) 7179.2,7704.3 7179.2,7733.5 cw(c7185.2,7733.5) 7191.2,7733.5 7191.2,7704.3 ccw(c7197.2,7704.3) 7203.2,7704.3 7203.2,7733.5 cw(c7209.2,7733.5) 7215.2,7733.5 7215.2,7704.3 ccw(c7221.2,7704.3) 7227.2,7704.3 7227.2,7733.5 cw(c7233.2,7733.5) 7239.2,7733.5 7239.2,7724.9 ccw(c7245.2,7724.9) 7245.2,7718.9 7257.8,7718.9 7295,7681.7 7475.7,7681.7 7482.1,7688.1 7527,7688.1 v1(7537.6,7677.4)
  other v1: 7071.5,7797.6
SDQ1: U10.F10 U34.V7 | length 847.4
  Top Layer w4: v1@7031.9,7797.6 7031.9,7816 U34.V7@7032.2,7816.3 ; v1(7567.5,7651.5) 7571.9,7651.5 U10.F10@7584.9,7664.5
  Inner2 w4: v1@7031.9,7797.6 7031.9,7776.5 7045.5,7762.8 7045.5,7678.1 7064.2,7659.4 7064.2,7634.5 7072.9,7625.7 7087.5,7625.7 7100.5,7638.7 7127.8,7638.7 cw(c7127.8,7632.7) 7133.8,7632.7 7133.8,7620.1 ccw(c7139.8,7620.1) 7145.8,7620.1 7145.8,7632.7 cw(c7151.8,7632.7) 7157.8,7632.7 7157.8,7620.1 ccw(c7163.8,7620.1) 7169.8,7620.1 7169.8,7632.7 cw(c7175.8,7632.7) 7175.8,7638.7 7289.7,7638.7 7313.1,7615.3 7443.6,7615.3 7461.1,7632.8 7482.4,7632.8 7492.6,7622.6 7548.9,7622.6 7561.9,7635.5 7561.9,7645.9 v1(7567.5,7651.5)
  other v1: 7032.2,7797.6
SDQ2: U10.F8 U34.Y5 | length 844.6
  Top Layer w4: v1(7052.1,7776.9) 7052.4,7777.2 U34.Y5@7072,7777.2 ; U10.F8@7647.9,7664.5 7660.8,7651.6 v1(7663.6,7651.6)
  Inner2 w4: v1(7052.1,7776.9) 7057.8,7771.3 7057.8,7686.1 7093.1,7650.8 7297.5,7650.8 7311.8,7636.5 7444.5,7636.5 7456.4,7648.4 7482,7648.4 7498.4,7632 7542.6,7632 7552.1,7641.5 7552.1,7680.2 7562.8,7691 7639.3,7691 7646.8,7683.4 7646.8,7668.4 v1(7663.6,7651.6)
SDQ3: U10.E11 U34.W7 | length 775.3
  Top Layer w4: v1@7051.6,7797.6 7051.6,7816 U34.W7@7051.8,7816.3 ; v1(7537.6,7651.8) 7540.5,7651.8 U10.E11@7553.4,7638.9
  Inner2 w4: v1@7051.6,7797.6 7070.4,7778.8 7070.4,7756 7079.9,7746.5 7085.4,7746.5 7088.6,7743.3 7088.6,7737.4 7084.2,7733.1 7075.1,7733.1 7071.7,7729.7 7071.7,7720.4 7074.7,7717.5 7086.5,7717.5 7090.1,7713.9 7090.1,7702.9 7087.3,7700.1 7077,7700.1 7072.9,7696 7072.9,7688.3 7097.7,7663.5 7110.6,7663.5 7113.7,7666.6 7113.7,7674.5 7118.1,7678.9 7125,7678.9 7129.3,7674.6 7129.3,7666.8 7132.6,7663.5 7161,7663.5 7166.6,7669.1 7166.6,7680.4 7169.8,7683.6 7180.9,7683.6 7184.5,7680 7184.5,7674.9 7196,7663.5 7216.5,7663.5 7222.9,7669.9 7222.9,7682.1 7225.2,7684.4 7240.7,7684.4 7245,7680.1 7245,7670.3 7251.6,7663.7 7251.6,7663.5 7305.6,7663.5 7319.8,7649.3 7435.8,7649.3 7446.8,7660.3 7529.1,7660.3 v1(7537.6,7651.8)
  other v1: 7051.8,7797.6
SDQ4: U10.E10 U34.W1 | length 816
  Top Layer w3.5: U34.W1@7051.8,7698.1 7051.8,7687.2 7057.3,7681.7 7057.3,7662.5 7068.4,7651.4
  Top Layer w4: 7068.4,7651.4 7068.4,7600 7098.9,7569.5 v1(7125.3,7569.5) ; U10.E10@7584.9,7638.9 7597.4,7651.4 v1(7602.6,7651.4)
  Inner2 w4: v1(7125.3,7569.5) 7125.5,7569.7 7336.8,7569.7 7343.1,7563.5 7356.4,7563.5 cw(c7356.4,7557.5) 7362.4,7557.5 7362.4,7554.6 ccw(c7368.4,7554.6) 7374.4,7554.6 7374.4,7557.5 cw(c7380.4,7557.5) 7386.4,7557.5 7386.4,7554.6 ccw(c7392.4,7554.6) 7398.4,7554.6 7398.4,7557.5 cw(c7404.4,7557.5) 7410.4,7557.5 7410.4,7554.6 ccw(c7416.4,7554.6) 7422.4,7554.6 7422.4,7557.5 cw(c7428.4,7557.5) 7434.4,7557.5 7434.4,7554.6 ccw(c7440.4,7554.6) 7446.4,7554.6 7446.4,7557.5 cw(c7452.4,7557.5) 7452.4,7563.5 7513.3,7563.5 7521.5,7571.7 7564.3,7571.7 7602.6,7610 v1(7602.6,7651.4)
SDQ5: U10.F9 U34.W4 | length 901.4
  Top Layer w4: v1@7032.1,7757.2 U34.W4@7051.8,7757.2 ; U10.F9@7616.4,7664.5 7629.3,7677.4 v1(7632.1,7677.4)
  Inner2 w4: v1(7032,7757.2) 7032,7674 7049.3,7656.8 7049.3,7612.7 7108.1,7553.9 7232.4,7553.9 7253.5,7532.7 7499.2,7532.7 7526.4,7559.9 7571,7559.9 7618.6,7607.5 7618.6,7663.9 v1(7632.1,7677.4)
SDQ6: U10.D9 U34.W2 | length 823.1
  Top Layer w3.5: 7049.7,7673.7 7049.7,7679.4 7041.5,7687.6 7041.5,7702.4 7051.8,7712.7 U34.W2@7051.8,7717.8
  Top Layer w4: 7049.7,7673.7 7049.7,7655.3 7057.5,7647.5 7057.5,7588.2 7096.2,7549.5 7122.3,7549.5 v1(7133.9,7537.9) ; U10.D9@7616.4,7613.3 7629.3,7626.2 v1(7632.1,7626.2)
  Inner2 w4: v1(7133.9,7537.9) 7217.4,7537.9 7236.4,7518.8 7502.8,7518.8 7533.6,7549.6 7578.9,7549.6 7632.1,7602.7 v1(7632.1,7626.2)
SDQ7: U10.E9 U34.W3 | length 924.7
  Top Layer w3.5: 7041.9,7672.6 7041.9,7674.8 7032.7,7684.1 7032.7,7704.2 7042,7713.6 7042,7727.7 U34.W3@7051.8,7737.5
  Top Layer w4: 7041.9,7672.6 7041.9,7583.2 7090.9,7534.2 7114.4,7534.2 v1(7136.5,7512.2) ; U10.E9@7616.4,7638.9 7629.3,7651.8 v1(7632.1,7651.8)
  Inner2 w4: v1(7136.5,7512.2) 7213.4,7512.2 7221.5,7504.1 7506.3,7504.1 7540.3,7538.1 7589,7538.1 7646.8,7595.9 7646.8,7637.1 v1(7632.1,7651.8)
SDQ8: U10.C8 U34.AA1 | length 930.2
  Top Layer w4: U34.AA1@7091.2,7698.1 7091.2,7676.7 7117.4,7650.6 7117.4,7627.3 7130.2,7614.5 7130.2,7595.8 7334.2,7391.8 7602.2,7391.8 7692.6,7482.2 7692.6,7548.7 7653.5,7587.7 U10.C8@7647.9,7587.7
SDQ9: U10.C11 U34.AB4 | length 759.4
  Top Layer w3.5: U34.AB4@7110.9,7757.2 7112.8,7757.2 7115.9,7754.1 7117.7,7753.7 7207.5,7753.7 7219.1,7742.1
  Top Layer w4: 7219.1,7742.1 7302,7659.2 7397.7,7659.2 7416.9,7678.5 7416.9,7740.7 7420.6,7744.4 7432.2,7744.4 7436.7,7739.8 7436.7,7723.4 7440.3,7719.8 7447.6,7719.8 7451.1,7723.2 7451.1,7741.4 7455.4,7745.7 7462,7745.7 7471.6,7736.1 7471.6,7646.4 7466.9,7641.6 7461.1,7641.6 7455.1,7635.7 7455.1,7614.3 7468.9,7600.6 7529.9,7600.6 7542.7,7587.7 U10.C11@7553.4,7587.7
SDQ10: U10.C9 U34.AB1 | length 857
  Top Layer w4: U34.AB1@7110.9,7698.1 7110.9,7682.2 7139.3,7653.7 7139.3,7636.4 7153.7,7622 7153.7,7615.4 7351,7418.1 7594.8,7418.1 7671.5,7494.7 7671.5,7531.9 7655.1,7548.4 7640.1,7548.4 7632.1,7556.3 7632.1,7574.4 U10.C9@7617.6,7589
SDQ11: U10.B10 U34.AB3 | length 782.4
  Top Layer w3.5: U34.AB3@7110.9,7737.5 7120.6,7727.8 7141.5,7727.8
  Top Layer w4: 7141.5,7727.8 7179.9,7727.8 7335.9,7571.8 7344.2,7571.8 7355.2,7582.9 7362,7582.9 7368.2,7576.7 7368.2,7569.9 7356.7,7558.4 7356.7,7549.3 7365.5,7540.4 7376,7540.4 7385.3,7549.7 7385.3,7570.9 7391.4,7577.1 7398.7,7577.1 7404.9,7570.8 7404.9,7542.4 7390.6,7528.1 7390.6,7513.4 7402.7,7501.3 7413.5,7501.3 ccw(c7413.5,7508.6) 7420.8,7508.6 7420.8,7515 cw(c7427.2,7515) 7427.2,7521.4 7430.6,7521.4 ; 7430.6,7521.3 cw(c7430.6,7513.6) 7438.3,7513.6 7438.3,7511.4 ccw(c7448.4,7511.4) 7448.4,7501.3 7548.3,7501.3 7568,7521 7568,7556 7574.2,7562.2 U10.B10@7584.9,7562.2
SDQ12: U10.B11 U34.AC3 | length 796.6
  Top Layer w4: U34.AC3@7130.6,7737.5 7180.7,7737.5 7187.3,7737.5 7309.6,7615.2 7322.4,7615.2 ccw(c7322.4,7621.2) 7328.4,7621.2 7328.4,7632.7 cw(c7334.4,7632.7) 7340.4,7632.7 7340.4,7606.8 ccw(c7346.4,7606.8) 7352.4,7606.8 7352.4,7632.7 cw(c7358.4,7632.7) 7364.4,7632.7 7364.4,7606.8 ccw(c7370.4,7606.8) 7376.4,7606.8 7376.4,7632.7 cw(c7382.4,7632.7) 7388.4,7632.7 7388.4,7621.2 ccw(c7394.4,7621.2) 7394.4,7615.2 7405.7,7615.2 7421.4,7599.5 7421.4,7585.9 ccw(c7427.3,7585.9) 7427.3,7580 ; 7427.3,7579.9 7442.1,7579.9 7445.9,7576.2 7445.9,7560.2 7441.7,7556 7425.2,7556 ccw(c7425.2,7549.2) 7418.4,7549.2 7418.4,7539.9 ccw(c7423.2,7539.9) 7423.2,7535.1 7438.7,7535.1 ; 7438.7,7535 cw(c7438.7,7525.7) 7448,7525.7 7448,7523.7 ccw(c7457.9,7523.7) 7457.9,7513.8 7520,7513.8 7537.9,7531.7 7537.9,7546.7 U10.B11@7553.4,7562.2
SDQ13: U10.C10 U34.AA4 | length 798.2
  Top Layer w3.5: U34.AA4@7091.2,7757.2 7101.1,7747.3 7114.2,7747.3 7114.8,7746.7 7196.2,7746.7 7205.8,7737.1
  Top Layer w4: 7205.8,7737.1 7296.6,7646.3 7403.6,7646.3 7433.1,7675.8 7433.1,7701.6 7438.5,7707.1 7447.6,7707.1 7454.1,7700.6 7454.1,7655.7 7438.4,7639.9 7438.4,7606.7 7457.3,7587.8 7457.3,7535.5 7467.2,7525.6 7498.4,7525.6 7504.6,7531.8 7504.6,7540.8 7513.8,7550 7528.8,7550 7536.6,7557.7 7536.6,7565 7546.8,7575.3 7572.4,7575.3 U10.C10@7584.9,7587.7
SDQ14: U10.B9 U34.AA3 | length 831.5
  Top Layer w3.5: U34.AA3@7091.2,7737.5 7101.1,7727.6 7101.1,7712.5 7105.7,7708 7115.1,7708 7120.7,7702.4 7120.7,7689.7
  Top Layer w4: 7120.7,7689.7 7120.7,7685.4 7149.1,7657 7149.1,7645.1 7164.7,7629.5 7164.7,7623.9 7357.4,7431.2 7590.4,7431.2 7628.5,7469.3 7628.5,7480.7 7632.9,7485.1 7643.9,7485.1 7644.1,7484.9 7649.9,7490.7 7649.9,7499.4 7636.6,7512.6 7636.6,7523.3 7630.2,7529.7 7630.2,7542.7 7616.4,7556.5 U10.B9@7616.4,7562.2
SDQ15: U10.B8 U34.AA2 | length 887.4
  Top Layer w3.5: U34.AA2@7091.2,7717.8 7091.2,7712.5 7101,7702.7 7101,7689
  Top Layer w4: 7101,7689 7101,7680.4 7128.9,7652.5 7128.9,7629.8 7142.2,7616.5 7142.2,7605.2 7342.5,7404.8 7598,7404.8 7681.6,7488.3 7681.6,7543.5 7662.9,7562.2 U10.B8@7647.9,7562.2
SDQ16: U10.R8 U34.AC9 | length 836.4
  Top Layer w4: U34.AC9@7130.6,7855.6 7131.3,7854.9 7198.2,7854.9 7269,7925.8 7297.5,7925.8 7372.9,8001.2 7372.9,8038.5 7416.2,8081.9 7608.4,8081.9 7687.4,8002.8 7687.4,7923.7 7658.6,7894.8 U10.R8@7647.9,7894.8
SDQ17: U10.R9 U34.AB9 | length 852.9
  Top Layer w4: U34.AB9@7111.1,7854.7 7121,7844.7 7204.6,7844.7 7276,7916 7304.5,7916 7385.8,7997.4 7385.8,8032.8 7421.3,8068.2 7603.2,8068.2 7675.9,7995.6 7675.9,7928.4 7655.6,7908.2 7629.7,7908.2 U10.R9@7616.4,7894.8
SDQ18: U10.T9 U34.AA8 | length 758.3
  Top Layer w3.5: U34.AA8@7091.2,7835.9 7101,7826.1 7129.9,7826.1 7131.7,7827.9
  Top Layer w4: 7131.7,7827.9 7220,7827.9 7284.2,7892.1 7316.2,7892.1 7414.3,7990.2 7414.3,8019.8 7437.8,8043.3 7590,8043.3 7633.6,7999.8 7633.6,7937.6 U10.T9@7616.4,7920.4
SDQ19: U10.T8 U34.AB8 | length 764.6
  Top Layer w4: U34.AB8@7110.9,7835.9 7111.3,7836.3 7212.6,7836.3 7280.2,7903.9 7310.6,7903.9 7399.3,7992.7 7399.3,8025.8 7428.7,8055.2 7597.5,8055.2 7662.4,7990.2 7662.4,7934.8 7648,7920.4 U10.T8@7647.9,7920.4
SDQ20: U10.R10 U34.AC5 | length 713.7
  Top Layer w4: U34.AC5@7130.6,7776.9 7131.6,7777.9 7236.9,7777.9 7246.5,7768.3 7253.8,7768.3 7259.3,7773.7 7271.3,7773.7 7280.6,7764.4 7287.1,7764.4 7290.1,7767.4 7290.1,7782.2 7311.8,7804 7404.7,7804 7412,7811.2 7430.2,7811.2 7441.3,7800.1 7453.8,7800.1 7457.4,7803.8 7457.4,7806.7 ccw(c7451.4,7806.7) 7451.4,7812.7 7447.8,7812.7 cw(c7447.8,7818.7) 7447.8,7824.7 7451.4,7824.7 ccw(c7451.4,7830.7) 7457.4,7830.7 7457.4,7836.5 7469.5,7848.5 7469.5,7851.4 ccw(c7463.5,7851.4) 7463.5,7857.4 7447.1,7857.4 cw(c7447.1,7863.4) 7447.1,7869.4 7463.5,7869.4 ccw(c7463.5,7875.4) 7463.5,7881.4 7447.1,7881.4 cw(c7447.1,7887.4) 7447.1,7893.4 7463.5,7893.4 ccw(c7463.5,7899.4) 7469.5,7899.4 7469.5,7903.4 7475.1,7909.1 7570.6,7909.1 U10.R10@7584.9,7894.8
SDQ21: U10.R11 U34.AB5 | length 777.6
  Top Layer w3.5: U34.AB5@7110.9,7776.9 7116.6,7776.9 7125.8,7767.7 7138.5,7767.7 7141.3,7770.4 7162.5,7770.4
  Top Layer w4: 7162.5,7770.4 7226.4,7770.4 7246.2,7750.6 7246.5,7750.4 ; 7246.26,7750.66 ccw(c7250.5,7754.9) 7254.74,7750.66 ; 7254.7,7750.6 7262.6,7758.6 ; 7262.66,7758.54 cw(c7266.9,7754.3) 7271.14,7750.06 ; 7263.16,7742.14 ccw(c7267.4,7737.9) 7271.64,7733.66 ; 7263.2,7742.2 7271.1,7750.1 ; 7271.7,7733.7 7279.6,7741.6 ; 7279.66,7741.54 cw(c7283.9,7737.3) 7288.14,7733.06 ; 7280.16,7716.66 cw(c7284.4,7720.9) 7280.16,7725.14 ; 7280.2,7716.7 7281.6,7715.3 7296.1,7715.3 7301.7,7720.9 7301.7,7779.2 7316.4,7793.9 7411.2,7793.9 7418.6,7801.3 7424.5,7801.3 7436.8,7789 7492.1,7789 7495.3,7792.1 7495.3,7798.5 7490.2,7803.5 7490.2,7805.4 7487.8,7807.8 7481.4,7807.8 7477.6,7804 7471.8,7804 7467.6,7808.2 7467.6,7833.1 7475.5,7841 7486.8,7841 7496.1,7850.3 7496.1,7857 7493.7,7859.5 7484.8,7859.5 7480.7,7863.5 7480.7,7869.7 7484.3,7873.2 7490.9,7873.2 7499.6,7881.9 7540.4,7881.9 U10.R11@7553.4,7894.8 ; 7280.2,7725.2 7288.1,7733.1
SDQ22: U10.T11 U34.AA6 | length 735.3
  Top Layer w3.5: U34.AA6@7091.2,7796.6 7101,7786.7 7118.5,7786.7 7119.1,7786.1 7154.6,7786.1
  Top Layer w4: 7154.6,7786.1 7276.8,7786.1 7308.6,7817.9 7343,7817.9 ccw(c7343,7823.9) 7349,7823.9 7349,7834 cw(c7355,7834) 7361,7834 7361,7823.9 ccw(c7367,7823.9) 7373,7823.9 7373,7834 cw(c7379,7834) 7385,7834 7385,7823.9 ccw(c7391,7823.9) 7391,7817.9 7394.9,7817.9 7402.4,7825.4 7402.4,7839 7406.4,7843 7415.6,7843 7419.6,7839 7419.6,7828.7 7422.7,7825.7 7427.9,7825.7 7435.9,7833.7 7441,7833.7 7445.9,7838.6 7445.9,7843.9 7441.5,7848.3 7430.7,7848.3 7427,7852 7427,7858.6 7429.1,7860.7 7429.1,7899.3 7458.8,7929 7458.8,7946.3 7472.4,7959.9 7499.5,7959.9 7505.9,7953.6 7505.9,7941.9 7514.4,7933.5 7530.7,7933.5 7542.3,7921.9 U10.T11@7554,7921.9
SDQ23: U10.T10 U34.AB6 | length 718
  Top Layer w3.5: U34.AB6@7111.9,7796.5 7114.6,7793.7 7120.4,7793.7 7120.8,7793.3 7122,7793.1 7150.4,7793.1 7150.9,7793.6 7156.4,7793.6
  Top Layer w4: 7156.4,7793.6 7268.1,7793.6 7307.6,7833.1 7307.6,7844.4 7311,7847.8 7318.1,7847.8 cw(c7318.1,7841.8) 7324.1,7841.8 7324.1,7833.4 ccw(c7330.1,7833.4) 7336.1,7833.4 7336.1,7841.8 cw(c7342.1,7841.8) 7342.1,7847.8 7361.2,7847.8 7370.8,7857.4 ; 7370.76,7857.44 cw(c7375,7853.2) 7379.24,7857.44 ; 7379.3,7857.4 7385.1,7851.6 ; 7385.16,7851.56 ccw(c7389.4,7855.8) 7393.64,7860.04 ; 7388.62,7881.92 ccw(c7385.3,7878.6) 7381.98,7881.92 7380.2,7880.1 ccw(c7383.5,7876.8) 7380.18,7873.48 7393.6,7860 ; 7388.7,7881.9 7402.1,7868.5 ; 7397.2,7890.4 7410.6,7877 ; 7397.18,7890.48 cw(c7400.5,7893.8) 7397.18,7897.12 7399,7898.9 cw(c7402.3,7895.6) 7405.62,7898.92 ; 7402.06,7868.56 ccw(c7406.3,7872.8) 7410.54,7877.04 ; 7405.68,7898.88 ccw(c7409,7902.2) 7412.32,7898.88 7445.3,7931.9 7445.3,7951.3 7465.5,7971.5 7512.5,7971.5 7534,7950 7534,7942.3 7543.5,7932.9 7572.4,7932.9 U10.T10@7584.9,7920.4
SDQ24: U10.P9 U34.Y11 | length 729.8
  Top Layer w4: v1(7071.5,7876.6) U34.Y11@7071.5,7895 U34.Y11@7071.8,7895.3 ; U10.P9@7616.4,7869.2 7629.3,7856.3 v1(7632.1,7856.3)
  Inner2 w4: v1(7071.5,7876.6) 7150.6,7876.6 7167.8,7893.8 7167.8,7907.9 7202.6,7942.6 7293.8,7942.6 ccw(c7293.8,7949.6) 7300.8,7949.6 ; 7300.8,7949.7 cw(c7307.8,7949.7) 7314.8,7949.7 ; 7314.8,7949.6 ccw(c7321.8,7949.6) 7328.8,7949.6 ; 7328.8,7949.7 cw(c7335.8,7949.7) 7342.8,7949.7 ; 7342.8,7949.6 ccw(c7349.8,7949.6) 7356.8,7949.6 ; 7356.8,7949.7 cw(c7363.8,7949.7) 7370.8,7949.7 ; 7370.8,7949.6 ccw(c7377.8,7949.6) 7377.8,7942.6 7384.9,7942.6 7407.8,7919.8 7585.8,7919.8 7632.1,7873.5 v1(7632.1,7856.3)
SDQ25: U10.M10 U34.W9 | length 773.3
  Top Layer w4: v1(7051.6,7837) 7051.6,7855.3 U34.W9@7051.8,7855.6 ; v1(7566.1,7831.1) 7571.8,7831.1 U10.M10@7584.9,7818.1
  Inner2 w4: v1(7051.6,7837) 7065.1,7850.5 7165.2,7850.5 7209.2,7806.5 7244.9,7806.5 7257.8,7793.5 7275.7,7793.5 cw(c7275.7,7786.5) 7282.7,7786.5 7282.7,7782.1 ccw(c7289.7,7782.1) 7296.7,7782.1 7296.7,7786.5 cw(c7303.7,7786.5) 7303.7,7793.5 7323.4,7793.5 cw(c7323.4,7786.5) 7330.4,7786.5 7330.4,7782.5 ccw(c7337.4,7782.5) 7344.4,7782.5 7344.4,7786.5 cw(c7351.4,7786.5) 7358.4,7786.5 7358.4,7782.5 ccw(c7365.4,7782.5) 7372.4,7782.5 7372.4,7786.5 cw(c7379.4,7786.5) 7386.4,7786.5 7386.4,7782.5 ccw(c7393.4,7782.5) 7400.4,7782.5 7400.4,7786.5 cw(c7407.4,7786.5) 7414.4,7786.5 7414.4,7782.5 ccw(c7421.4,7782.5) 7428.4,7782.5 7428.4,7786.5 cw(c7435.4,7786.5) 7442.4,7786.5 7442.4,7782.5 ccw(c7449.4,7782.5) 7456.4,7782.5 7456.4,7786.5 cw(c7463.4,7786.5) 7470.4,7786.5 7470.4,7782.5 ccw(c7477.4,7782.5) 7484.4,7782.5 7484.4,7786.5 cw(c7491.4,7786.5) 7491.4,7793.5 7511.1,7793.5 7521.5,7804 7521.5,7808.2 7530.6,7817.2 7552.2,7817.2 v1(7566.1,7831.1)
SDQ26: U10.M9 U34.V9 | length 730.5
  Top Layer w4: v1(7031.9,7837) 7031.9,7855.3 U34.V9@7032.2,7855.6 ; U10.M9@7616.4,7818.1 7629.3,7805.2 v1(7632.1,7805.2)
  Inner2 w4: v1(7031.9,7837) 7046,7822.8 7101.4,7822.8 7149.6,7774.6 7240.5,7774.6 7286.7,7728.4 7458.3,7728.4 7476.5,7746.5 7597,7746.5 7616,7765.6 7616,7789 v1(7632.1,7805.2)
SDQ27: U10.M11 U34.Y9 | length 761.4
  Top Layer w4: v1(7071.2,7837) 7071.2,7855.3 U34.Y9@7071.5,7855.6 ; v1(7537.6,7803.7) 7539,7803.7 U10.M11@7553.4,7818.1
  Inner2 w4: v1(7071.2,7837) 7157,7837 7158.3,7835.6 ; 7145.1,7812.4 7158.3,7825.7 ; 7145.15,7812.45 ccw(c7150.1,7807.5) 7155.05,7802.55 ; 7155,7802.5 7168.2,7815.8 ; 7158.35,7825.65 ccw(c7153.4,7830.6) 7158.35,7835.55 ; 7168.25,7815.75 cw(c7173.2,7810.8) 7178.15,7815.75 ; 7178.1,7815.8 7178.3,7815.6 ; 7178.28,7815.68 cw(c7173.4,7810.8) 7178.28,7805.92 ccw(c7183.2,7801) 7178.32,7796.12 7178.4,7796 ccw(c7183.3,7800.9) 7188.18,7796.02 cw(c7193.1,7791.1) 7197.98,7795.98 ; 7197.9,7796 7202.7,7791.2 7241.7,7791.2 7273.9,7759.1 7321.8,7759.1 cw(c7321.8,7752.1) 7328.8,7752.1 7328.8,7747.6 ccw(c7335.8,7747.6) 7342.8,7747.6 7342.8,7752.1 cw(c7349.8,7752.1) 7356.8,7752.1 7356.8,7747.6 ccw(c7363.8,7747.6) 7370.8,7747.6 7370.8,7752.1 cw(c7377.8,7752.1) 7384.8,7752.1 7384.8,7747.6 ccw(c7391.8,7747.6) 7398.8,7747.6 7398.8,7752.1 cw(c7405.8,7752.1) 7412.8,7752.1 7412.8,7747.6 ccw(c7419.8,7747.6) 7426.8,7747.6 7426.8,7752.1 cw(c7433.8,7752.1) 7440.8,7752.1 7440.8,7747.6 ccw(c7447.8,7747.6) 7454.8,7747.6 7454.8,7752.1 cw(c7461.8,7752.1) 7461.8,7759.1 7509.5,7759.1 7521.5,7771.1 7521.5,7787.6 v1(7537.6,7803.7)
SDQ28: U10.N10 U34.AC11 | length 695.8
  Top Layer w4: U34.AC11@7132.2,7894.5 7152.8,7894.5 7177.5,7919.3 v1(7199.2,7919.3) ; U10.N10@7584.9,7843.6 7597.5,7831 v1(7602.9,7831)
  Inner2 w4: v1(7199.2,7919.3) 7203.3,7919.3 7232.4,7890.1 7235.1,7890.1 cw(c7235.1,7883.1) 7242.1,7883.1 7242.1,7872.4 ccw(c7249.1,7872.4) 7256.1,7872.4 7256.1,7883.1 cw(c7263.1,7883.1) 7263.1,7890.1 7263.7,7890.1 ; 7263.7,7890.2 cw(c7263.7,7883.5) 7270.4,7883.5 ccw(c7277.1,7883.5) 7277.1,7876.8 7277.7,7876.8 ccw(c7277.7,7883.5) 7284.4,7883.5 cw(c7291.1,7883.5) 7291.1,7890.2 ; 7291.1,7890.1 7394.2,7890.1 cw(c7394.2,7883.1) 7401.2,7883.1 7401.2,7881.7 ccw(c7408.2,7881.7) 7415.2,7881.7 7415.2,7883.1 cw(c7422.2,7883.1) 7429.2,7883.1 7429.2,7881.7 ccw(c7436.2,7881.7) 7443.2,7881.7 7443.2,7883.1 cw(c7450.2,7883.1) 7450.2,7890.1 7463.8,7890.1 7475.5,7878.5 7494.4,7878.5 7513,7897.2 7521.8,7897.2 7524.3,7894.7 7524.3,7889 7527,7886.3 7534.7,7886.3 7536.8,7888.4 7536.8,7894.3 7539.7,7897.2 7546.5,7897.2 7550.2,7893.6 7550.2,7889.4 7552.4,7887.1 7558,7887.1 7560.7,7889.8 7560.7,7893.9 7564,7897.2 7571.2,7897.2 7602.9,7865.5 v1(7602.9,7831)
SDQ29: U10.M8 U34.W11 | length 775.4
  Top Layer w4: v1(7051.8,7876.6) U34.W11@7051.8,7895 U34.W11@7052.1,7895.3 ; U10.M8@7647.9,7818.1 7660.8,7830.9 v1(7663.6,7830.9)
  Inner2 w4: v1(7051.8,7876.6) 7066.1,7890.8 7145.6,7890.8 7155.6,7900.8 7155.6,7915.4 7195.9,7955.8 7236.2,7955.8 7253.4,7973.1 7379.1,7973.1 7402.4,7949.8 7496,7949.8 7513.5,7932.3 7590.1,7932.3 7647.7,7874.7 7647.7,7846.8 v1(7663.6,7830.9)
SDQ30: U10.N9 U34.AB11 | length 731.4
  Top Layer w3.5: U34.AB11@7110.9,7895 7116.1,7895 7126.2,7905 7150.4,7905 7158,7912.7
  Top Layer w4: 7158,7912.7 7179.3,7934 7209.4,7934 v1(7220.3,7923.1) ; U10.N9@7616.4,7843.6 7629.3,7830.8 v1(7632.1,7830.8)
  Inner2 w4: v1(7220.3,7923.1) 7249.6,7923.1 7264.8,7907.8 7271.2,7907.8 ccw(c7271.2,7914.8) 7278.2,7914.8 7278.2,7921.4 cw(c7285.2,7921.4) 7292.2,7921.4 7292.2,7914.8 ccw(c7299.2,7914.8) 7306.2,7914.8 7306.2,7921.4 cw(c7313.2,7921.4) 7320.2,7921.4 7320.2,7914.8 ccw(c7327.2,7914.8) 7334.2,7914.8 7334.2,7921.4 cw(c7341.2,7921.4) 7348.2,7921.4 7348.2,7914.8 ccw(c7355.2,7914.8) 7362.2,7914.8 7362.2,7921.4 cw(c7369.2,7921.4) 7376.2,7921.4 7376.2,7914.8 ccw(c7383.2,7914.8) 7383.2,7907.8 7578.2,7907.8 7614.8,7871.3 7614.8,7848.1 v1(7632.1,7830.8)
SDQ31: U10.N11 U34.V11 | length 764.5
  Top Layer w4: v1(7032.2,7876.6) 7032.2,7895 U34.V11@7032.4,7895.3 ; v1(7537.6,7830.8) 7540.5,7830.8 U10.N11@7553.4,7843.6
  Inner2 w4: v1(7032.2,7876.6) 7046.4,7862.4 7171.1,7862.4 7207.6,7825.8 7277.7,7825.8 7297.3,7806.2 7305.1,7806.2 ccw(c7305.1,7813.2) 7312.1,7813.2 7312.1,7820.2 cw(c7319.1,7820.2) 7326.1,7820.2 7326.1,7813.2 ccw(c7333.1,7813.2) 7340.1,7813.2 7340.1,7820.2 cw(c7347.1,7820.2) 7354.1,7820.2 7354.1,7813.2 ccw(c7361.1,7813.2) 7368.1,7813.2 7368.1,7820.2 cw(c7375.1,7820.2) 7382.1,7820.2 7382.1,7813.2 ccw(c7389.1,7813.2) 7396.1,7813.2 7396.1,7820.2 cw(c7403.1,7820.2) 7410.1,7820.2 7410.1,7813.2 ccw(c7417.1,7813.2) 7424.1,7813.2 7424.1,7820.2 cw(c7431.1,7820.2) 7438.1,7820.2 7438.1,7813.2 ccw(c7445.1,7813.2) 7452.1,7813.2 7452.1,7820.2 cw(c7459.1,7820.2) 7466.1,7820.2 7466.1,7813.2 ccw(c7473.1,7813.2) 7473.1,7806.2 7482.6,7806.2 7501.9,7825.5 7518.7,7825.5 7523.9,7830.8 v1(7537.6,7830.8)
SDQM0: U10.G8 U34.U7 | length 816.1
  Top Layer w4: v1(7012.5,7797.6) U34.U7@7012.5,7816.3 ; U10.G8@7647.9,7690.1 7660.8,7677.2 v1(7663.6,7677.2)
  Inner2 w4: v1@7012.2,7797.6 7025.7,7811.1 7086.9,7811.1 7139.2,7758.8 7237.9,7758.8 7302.1,7694.6 7452.3,7694.6 7474.3,7716.7 7516.2,7716.7 7522.3,7722.9 7665.5,7722.9 7678.7,7709.6 7678.7,7692.3 v1(7663.6,7677.2)
SDQM1: U10.D8 U34.AA5 | length 813.4
  Top Layer w3.5: U34.AA5@7091.2,7776.9 7101.1,7767 7116.5,7767 7122.8,7760.7 7145.4,7760.7 7147.3,7762.6
  Top Layer w4: 7147.3,7762.6 7215.6,7762.6 7308.6,7669.5 7391.2,7669.5 7402.4,7680.7 7402.4,7745.3 7415.2,7758.1 7466.8,7758.1 7485.8,7739.1 7485.8,7636.8 7496.6,7626.1 7594.8,7626.1 7602.2,7618.7 7602.2,7609.3 7611,7600.4 7634.9,7600.4 U10.D8@7647.9,7613.3
SDQM2: U10.P8 U34.AA9 | length 928
  Top Layer w3.5: U34.AA9@7089.9,7855.9 7099.5,7865.5 7144.5,7865.5
  Top Layer w4: 7144.6,7865.4 7191.2,7865.4 7264.3,7938.6 7291.9,7938.6 7357.3,8004 7357.3,8041.2 7410,8093.9 7617.7,8093.9 7699.5,8012.2 7699.5,7920.9 U10.P8@7647.9,7869.3
SDQM3: U10.L8 U34.U11 | length 863.1
  Top Layer w4: v1(7012.5,7876.6) U34.U11@7012.5,7895 U34.U11@7012.8,7895.3 ; U10.L8@7647.9,7792.5 7660.8,7805.4 v1(7663.6,7805.4)
  Inner2 w4: v1(7012.5,7876.6) 7037.2,7901.3 7104.8,7901.3 7135.7,7932.2 7153.1,7932.2 7189.4,7968.5 7226,7968.5 7240.2,7982.7 7388.4,7982.7 7408.9,7962.3 7505.1,7962.3 7522.7,7944.7 7596.2,7944.7 7678.9,7862 7678.9,7820.6 v1(7663.6,7805.4)
SDQS0N: U10.G11 U34.Y3 | length 740.9
  Top Layer w3.5: U34.Y3@7071.5,7737.5 7081.3,7727.7 7081.3,7682.4
  Top Layer w4: 7081.3,7682.4 7081.3,7673.4 7108.5,7646.2 7108.5,7615.2 7114.2,7609.6 v1(7114.4,7609.6) ; U10.G11@7553.4,7690.1 7566.3,7677.2 v1(7569.1,7677.2)
  Inner2 w4: v1(7114.4,7609.6) 7109.8,7609.6 7104.1,7603.9 7104.1,7600 7108.1,7596 7184.2,7596 7200,7611.7 7288.8,7611.7 7303.7,7596.8 7446.3,7596.8 7454,7604.5 7555.5,7604.5 7573.3,7622.3 7573.3,7634 7581.5,7642.2 7581.5,7664.8 v1(7569.1,7677.2)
